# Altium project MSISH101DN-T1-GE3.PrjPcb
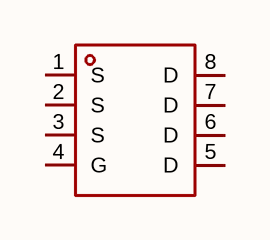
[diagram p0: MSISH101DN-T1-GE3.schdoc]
1 sheet, 1 parts. Net scope: global (net labels, ports and power ports of the same name join across sheets).

## Sheet MSISH101DN-T1-GE3.schdoc
size 127 x 101 mm

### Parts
Q?  msish101dn-t1-ge3  [POWERPAK-1212-8_L3.0-W3.0-P0.65-LS3.3-BL]  (value not drawn)

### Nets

Not connected (* = marked no-connect by the designer): Q? 1(S) 2(S) 3(S) 4(G) 5(D) 6(D) 7(D) 8(D)

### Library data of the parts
Q? = msish101dn-t1-ge3: 数量:1个P沟道;漏源电压(Vdss):30V;连续漏极电流(Id):70A;导通电阻(RDS(on)):6.5mΩ@10V;耗散功率(Pd):31.2W;阈值电压(Vgs(th)):1.6V;; Manufacturer: MSKSEMI(美森科); AddInBom: yes; ModelId: 74fc8db97a8d4d328d7f3b4acba39a5e; ModelTransform: 129.921,129.921,0,0,0,0,0,0,0; Number: 1个P沟道; Drain to Source Voltage: 30V; Current - Continuous Drain(Id): 70A; Pd - Power Dissipation: 31.2W; Gate Threshold Voltage (Vgs(th)): 1.6V; Gate Charge(Qg): 45nC; Input Capacitance(Ciss): 4.32nF; Reverse Transfer Capacitance (Crss@Vds): 487pF; Type: P沟道; Output Capacitance(Coss): 529pF; Vgs: ±20V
